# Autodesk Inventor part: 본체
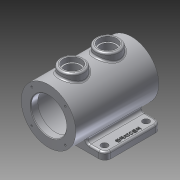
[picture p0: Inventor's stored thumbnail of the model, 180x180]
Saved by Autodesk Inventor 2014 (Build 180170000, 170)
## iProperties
Created: 2014-12
Part Number: 본체
Material: 알루미늄 6061
Document SubType Name: Modeling
Designer: Owner
Density: 2.71 g/cm^3
Appearance: 알루미늄 - 평지
Mass: 1293.23 g
Surface Area: 1041.82 cm^2
Volume: 477.206 cm^3
Author: Owner
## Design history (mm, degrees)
sketch "스케치1"
  geometry: C1 r 46 at (0, 0); 1 further point
  constraints: 1 centre point, 1 coincident
  dimensions: "d0" = 92 diameter of C1
extrude "돌출1" new body sketch "스케치1" distance "d1" = 140; taper "d2" = 0 deg
node "작업 평면1"
sketch "스케치2"
  geometry: L1 (65, -38)-(65, -50); L2 (65, -50)-(-65, -50); L3 (-65, -50)-(-65, -38); L4 (-65, -38)-(-38.884, -38); L5 (38.884, -38)-(65, -38); A1 r 46 centre (0, 0) between (-35.072, -29.765) and (35.072, -29.765) reference; A2 r 5 centre (-38.884, -33) between (-38.884, -38) and (-35.072, -29.765); A3 r 5 centre (38.884, -33) between (35.072, -29.765) and (38.884, -38); 2 further points
  constraints: 10 end point, 6 point on circle, 6 tangent, 3 parallel, 2 centre point, 2 horizontal, 2 perpendicular, 1 equal radius, 1 midpoint, 1 vertical alignment
  dimensions: "d4" = 50 distance from line of L2 point (0, 0); "d5" = 12 distance of L2.end L3.end; "d6" = 5 radius of A3; "d7" = 130 distance between parallel lines of L1 L3
extrude "돌출2" join sketch "스케치2" distance "d8" = 95; taper "d9" = 0 deg
node "작업 평면2"
sketch "스케치3"
  geometry: L1 (-46, 0)-(46, 0) reference; C1 r 20 at (0, 100); C2 r 20 at (0, 40); 1 further point
  constraints: 2 centre point, 2 vertical alignment, 1 equal radius
  dimensions: "d11" = 40 diameter of C1; "d12" = 40 distance from line of C2.centre L1; "d13" = 60 distance of C2.centre C1.centre
extrude "돌출3" join sketch "스케치3" stored distance "d14" = 95; taper "d15" = 0 deg
sketch "스케치4"
  geometry: L1 (26.116, 0)-(0, 0) reference; L2 (0, 95)-(26.116, 95) reference; 3 further points
  constraints: 1 vertical alignment
  dimensions: "d17" = 12.5 distance from line of L2 point (13.116, 82.5); "d18" = 12.5 distance from line of L1 point (13.116, 12.5); "d19" = 52 horizontal distance of point (13.116, 12.5) point (-38.884, -30)
hole "구멍1" sketch "스케치4" at (13.116, 82.5), (13.116, 12.5) diameter "d20" = 11; stored, may be unused: countersink angle "d24" = 90 deg, drill point angle "d26" = 0 deg; dims "d21" = 6, "d22" = 4, "d23" = 2, "d25" = 8
fillet "모깎기1" dims "d27" = 10
hole "구멍2" diameter "d30" = 30; stored, may be unused: countersink angle "d34" = 90 deg, drill point angle "d36" = 0 deg; dims "d28" = 10, "d29" = 10, "d31" = 6, "d32" = 4, "d33" = 2, "d35" = 8
hole "구멍3" diameter "d39" = 30; stored, may be unused: countersink angle "d43" = 90 deg, drill point angle "d45" = 0 deg; dims "d37" = 10, "d38" = 10, "d40" = 6, "d41" = 4, "d42" = 2, "d44" = 8
hole "구멍4" diameter "d48" = 60; stored, may be unused: countersink angle "d52" = 90 deg, drill point angle "d54" = 0 deg; dims "d46" = 10, "d47" = 10, "d49" = 6, "d50" = 4, "d51" = 2, "d53" = 12
hole "구멍5" diameter "d57" = 60; stored, may be unused: countersink angle "d61" = 90 deg, drill point angle "d63" = 0 deg; dims "d55" = 10, "d56" = 10, "d58" = 6, "d59" = 4, "d60" = 2, "d62" = 12
hole "구멍6" diameter "d66" = 75; stored, may be unused: countersink angle "d70" = 90 deg, drill point angle "d72" = 0 deg; dims "d64" = 10, "d65" = 10, "d67" = 6, "d68" = 4, "d69" = 2, "d71" = 116
hole "구멍7" diameter "d75" = 25; stored, may be unused: countersink angle "d79" = 90 deg, drill point angle "d81" = 0 deg; dims "d73" = 10, "d74" = 10, "d76" = 6, "d77" = 4, "d78" = 2, "d80" = 116
hole "구멍8" diameter "d84" = 25; stored, may be unused: countersink angle "d88" = 90 deg, drill point angle "d90" = 0 deg; dims "d82" = 10, "d83" = 10, "d85" = 6, "d86" = 4, "d87" = 2, "d89" = 116
sketch "스케치5"
  geometry: L1 (26.116, 10)-(26.116, 85) reference; C1 r 5.5 at (13.116, 12.5) reference; 2 further points
  constraints: 1 other
  dimensions: "d91" = 35 vertical distance of C1.centre point (18.116, 47.5); "d92" = 8 distance from line of L1 point (18.116, 47.5)
feature "엠보싱1" sketch "스케치5" dims "d1" = 140, "d93" = 1, "d94" = 0
sketch "스케치6"
  geometry: L1 (0, 0)-(28.284, 28.284); L2 (0, 0)-(40, 0); C1 r 46 at (0, 0) reference; 1 further point
  constraints: 4 end point, 1 coincident, 1 equal length, 1 horizontal
  dimensions: "d95" = 40 distance of L1.start L1.end; "d96" = 45 deg angle of L2 L1
hole "구멍9" sketch "스케치6" at (28.284, 28.284) diameter "d97" = 3.242; stored, may be unused: countersink angle "d101" = 90 deg, drill point angle "d103" = 0 deg; dims "d98" = 8, "d99" = 4, "d100" = 2, "d102" = 10
sketch "스케치7"
  geometry: L1 (0, 0)-(28.284, 28.284); L2 (0, 0)-(40, 0); C1 r 46 at (0, 0) reference; 1 further point
  constraints: 4 end point, 1 coincident, 1 equal length, 1 horizontal
  dimensions: "d107" = 40 distance of L1.start L1.end; "d108" = 45 deg angle of L2 L1
hole "구멍10" sketch "스케치7" at (28.284, 28.284) diameter "d109" = 3.242; stored, may be unused: countersink angle "d113" = 90 deg, drill point angle "d115" = 0 deg; dims "d110" = 8, "d111" = 4, "d112" = 2, "d114" = 10
fillet "모깎기2" dims "d119" = 3
fillet "모깎기3" dims "d120" = 3
chamfer "모따기1" distance "d121" = 1; stored, may be unused: second distance "d122" = 2, angle "d123" = 45 deg
chamfer "모따기2" distance "d124" = 1; stored, may be unused: second distance "d125" = 2, angle "d126" = 45 deg
fillet "모깎기4" dims "d127" = 3
fillet "모깎기5" dims "d128" = 3
node "솔리드1"
mirror "대칭1"
pattern_circular "원형 패턴1" dims angle "d105" = 360 deg
pattern_circular "원형 패턴2" dims angle "d117" = 360 deg
other parameters: "d10" = 56
